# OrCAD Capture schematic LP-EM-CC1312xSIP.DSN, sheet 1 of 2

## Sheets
1 1_RF and Peripherals: size A3; title: LP-EM-CC1312PSIP
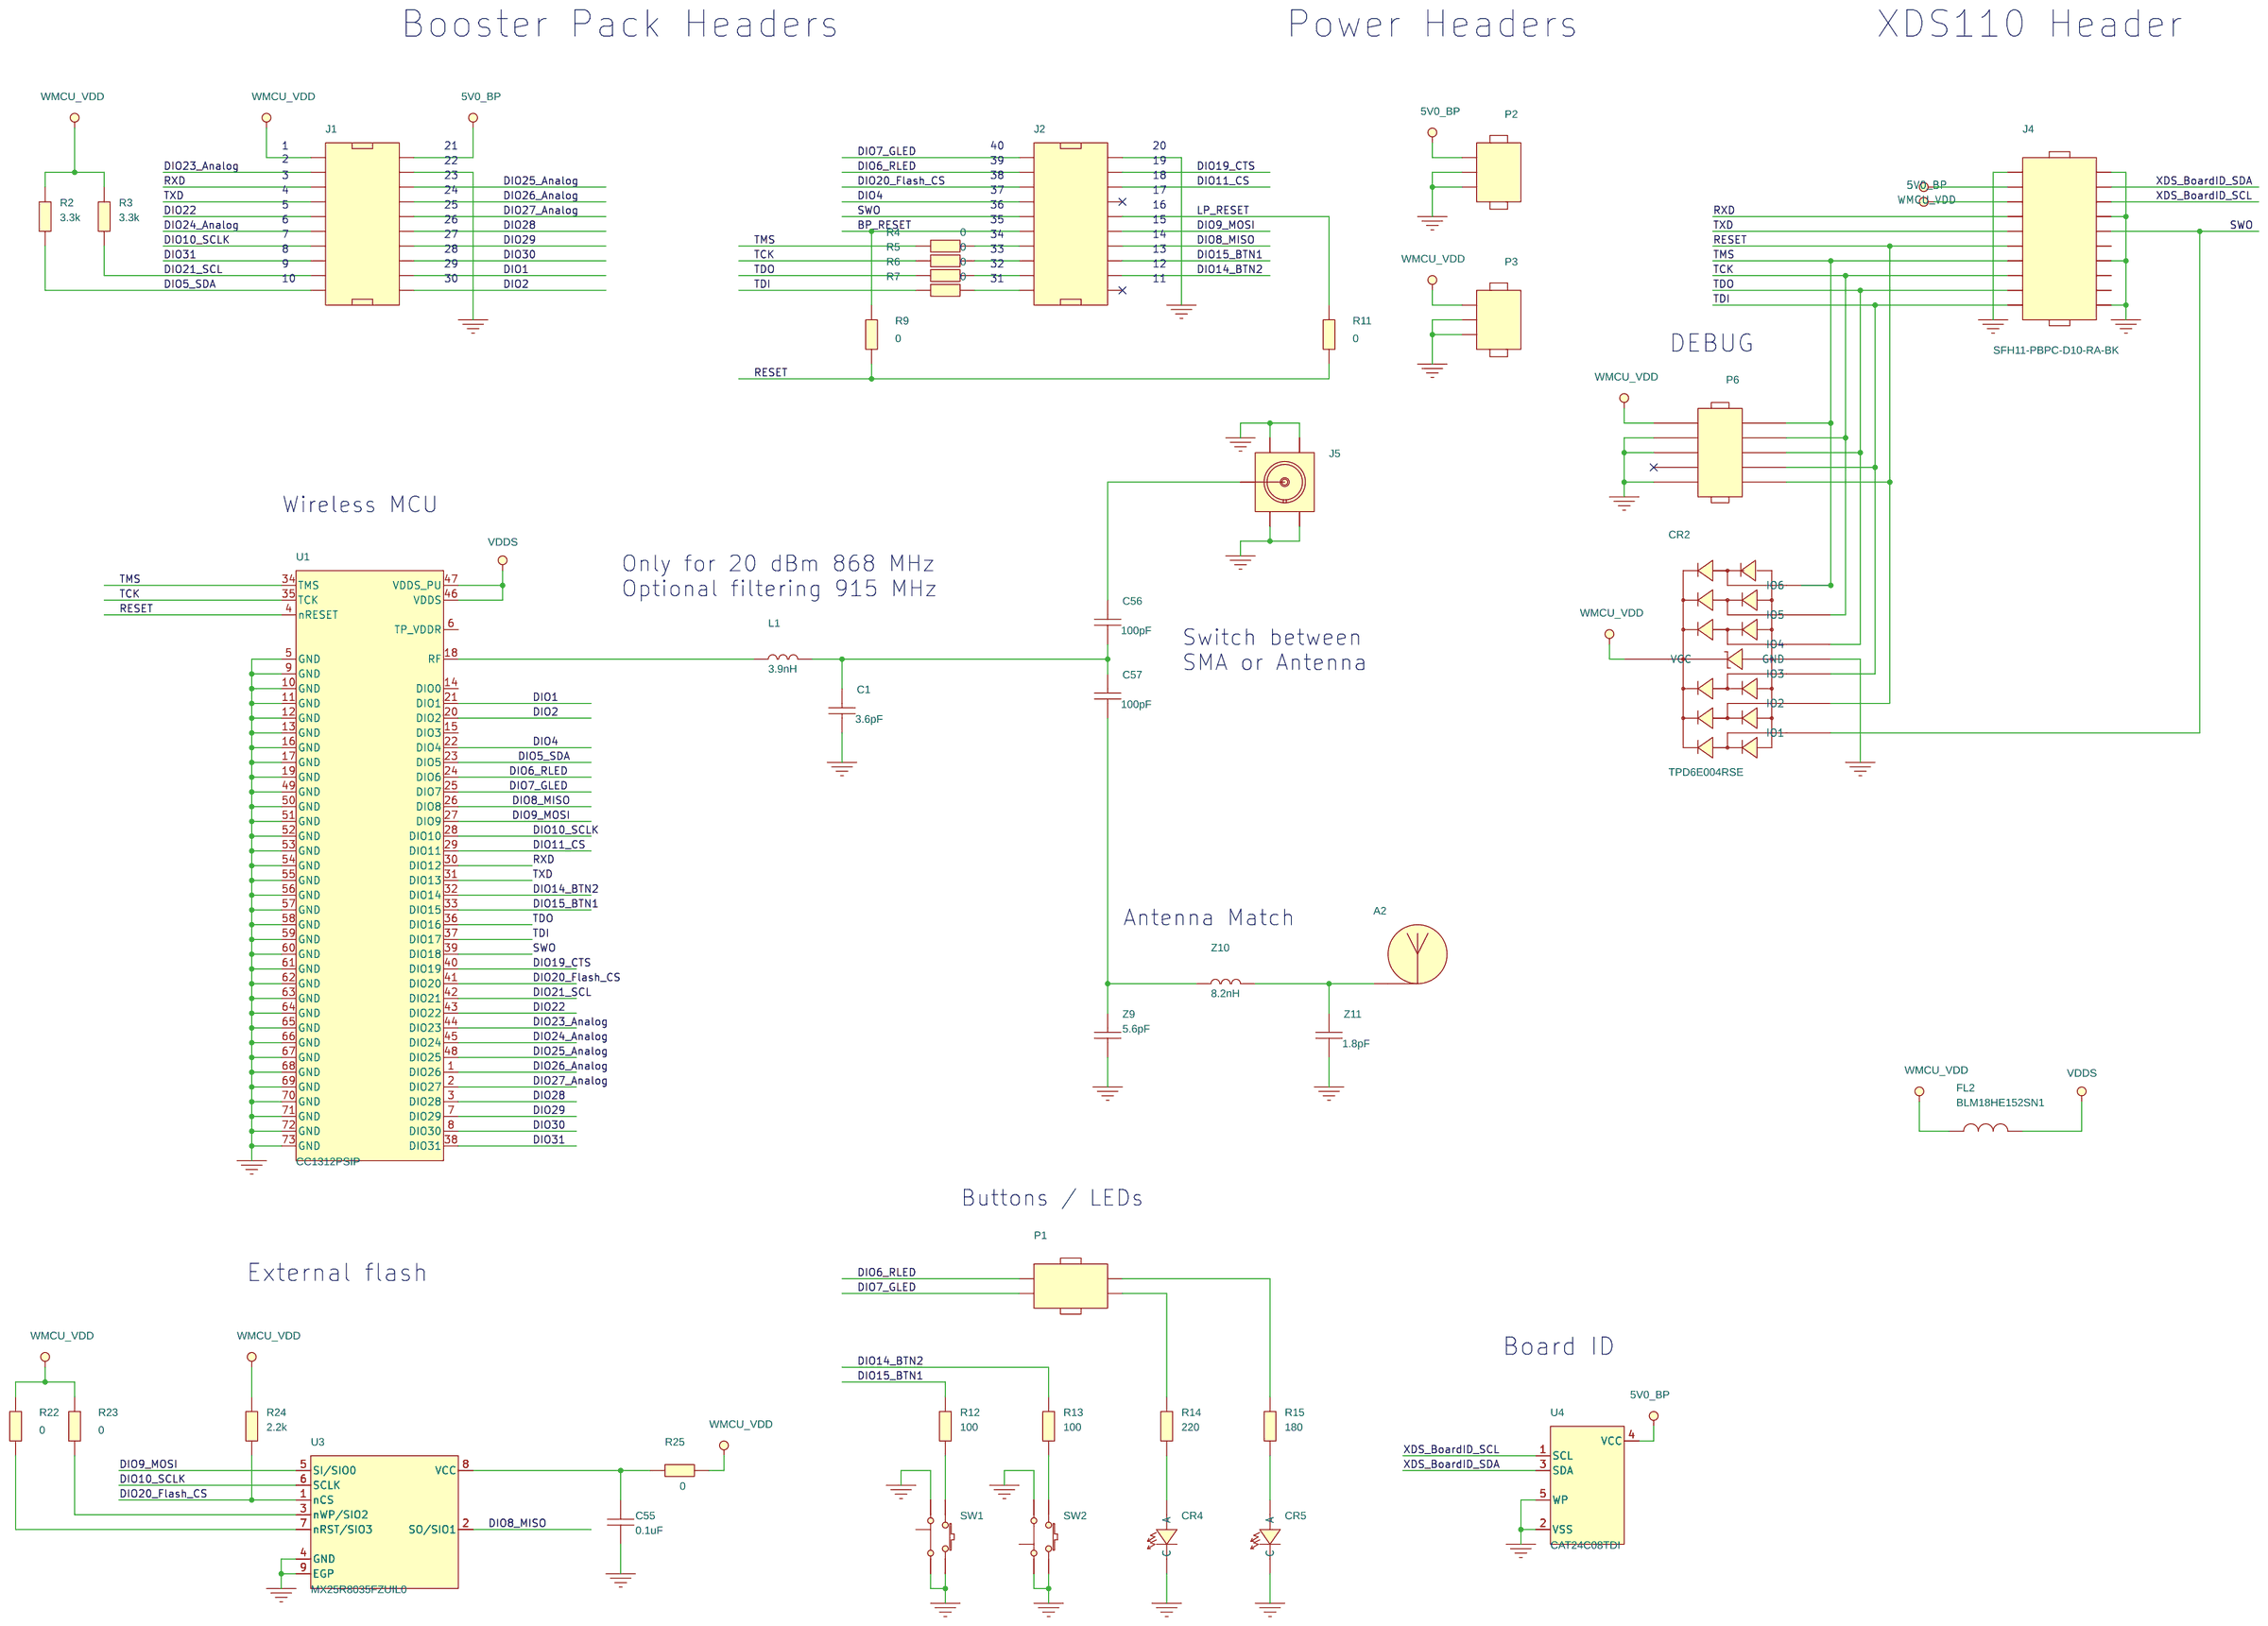
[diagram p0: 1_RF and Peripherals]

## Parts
A2  868MHz/2440MHz  [ANTENNA_DN024N]
C1  3.6pF  [CAPC0603X35B2N]
C55  0.1uF  [CAPC0603X35B2N]
C56  100pF  [CAPC0603X35B2N]
C57  100pF  [CAPC0603X35B2N]
CR2  TPD6E004RSE  [QFNFC50P150X150X60-8A2N]
CR4  LPL296-J2L2-25  [LEDC1707X65N]
CR5  LS L296-P2Q2-1  [LEDC1708X67N]
FL2  BLM18HE152SN1  [FIL_BLM18HE152SN1DN]
J1  SSQ-110-23-L-D  [SAMTEC_SSQ11023LD_A2B]
J2  SSQ-110-23-L-D  [SAMTEC_SSQ11023LD_A2B]
J4  SFH11-PBPC-D10-RA-BK  [SULLINS_SFH11PBPCD10RABK_A2B]
J5  SMA-10V21-TGG  [HUSTSAN_SMA10V21TGGAN]
L1  3.9nH  [INDC0603X33A2N]
P1  BB02-HJ041-KB1-603000  [GRADCONN_BB02HJ041KB1603000_A2B]
P2  BB02-HC031-KB1-603000  [GRADCONN_BB02HC031KB1603000_A2B]
P3  BB02-HC031-KB1-603000  [GRADCONN_BB02HC031KB1603000_A2B]
P6  FTSH-105-01-F-DV-K  [SAMTEC_FTSH10501FDVK_A2N]
R2  3.3k  [RESC1005X40B2N]
R3  3.3k  [RESC1005X40B2N]
R4  0  [RESC0603X35B2N]
R5  0  [RESC0603X35B2N]
R6  0  [RESC0603X35B2N]
R7  0  [RESC0603X35B2N]
R9  0  [RESC0603X35B2N]
R11  0  [RESC0603X35B2N]
R12  100  [RESC1005X40B2N]
R13  100  [RESC1005X40B2N]
R14  220  [RESC1005X40B2N]
R15  180  [RESC1005X40B2N]
R22  0  [RESC0603X35B2N]
R23  0  [RESC0603X35B2N]
R24  2.2k  [RESC1005X40B2N]
R25  0  [RESC0603X35B2N]
SW1  1188E-1K2  [SW_1188E1K2V_A2N]
SW2  1188E-1K2  [SW_1188E1K2V_A2N]
U1  CC1312PSIP  [LGAFC73S50P700X700X151]
U3  MX25R8035FZUIL0  [SON50P300X200X60-9B2N]
U4  CAT24C08TDI  [SOT95P280X100-5A2N]
Z9  5.6pF  [CAPC0603X35B2N]
Z10  8.2nH  [INDC0603X33A2N]
Z11  1.8pF  [CAPC0603X35B2N]

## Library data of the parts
A2 = ANTENNA_PCB: ANTENNA, NON COMPONENT, DUAL BAND OPTION - 868MHz/2440MHz, NOT APPLY; Additional Datasheet URL: N/A; AutoDoc File: https://notefied-dynamic-precision.com/DB/Apps/Desktop/Item/Object.aspx?id=96668; BU Name: DYNAMIC PRECISION GDANSK; Budget Currency: N/A; Budget Price: N/A; Client Status: UNDER_REVIEW; Country of Origin: Missing Info; Datasheet URL: https://www.ti.com/lit/an/swra227e/swra227e.pdf; Datasheet URL 1: http://www.ti.com/lit/an/swra227e/swra227e.pdf; Datasheet URL 2: N/A; Exclusive for Customers: TEXAS INSTRUMENTS NORWAY; Mass: N/A; Max Oper Temp: N/A; Maximum Operating Temperature: N/A; Min Oper Temp: N/A; Minimum Operating Temperature: N/A; Mounting Type: NOT APPLY; NOTEfied URL: https://notefied-dynamic-precision.com/NOTEfiedWebInterface/part/show?partNumber=13-01029; Notes: Custom component designed upon client's request.; Packing Size: N/A; Packing Type: Missing Info; Part Number: 13-01029; Part Type: Mechanic|ANTENNA|NON COMPONENT; ROHS: Missing Info; Revision: R024; RoHS Status: MISSING_INFO; Status: Released; Texas Part Status: Under Review; Type: Mechanic; Vendor: TEXAS INSTRUMENTS; Vendor Part Number: DN024; Vendor Part Status: Active; Weight: N/A
C1 = CAPACITOR: CAPACITOR, CERAMIC C0G/NP0, 3.6pF, 50V, -0.1pF/+0.1pF, -55DEGC/+125DEGC, 0201, SMD; ALT_SYMBOLS: CAPC0603X35B2L,CAPC0603X35B2M; Additional Datasheet URL: https://www.murata.com/en-eu/products/productdetail?partno=GRM0335C1H3R6BA01%23; Country of Origin: China,Japan,Philippines; Datasheet URL: https://search.murata.co.jp/Ceramy/image/img/A01X/G101/ENG/GRM0335C1H3R6BA01-01A.pdf; Dielectric Type: C0G/NP0; Mass: 0.00033g; Maximum Operating Temperature: +125DEGC; Maximum Tolerance: +0.1pF; Minimum Operating Temperature: -55DEGC; Minimum Tolerance: -0.1pF; Mounting Type: SMD; NOTEfied URL: https://notefied-dynamic-precision.com/NOTEfiedWebInterface/part/show?partNumber=02-06150; PCB Package: 0201; Packing Size: 50000; Packing Type: Tape & Reel; Part Number: 02-06150; Part Type: Capacitor|CERAMIC|0201|STANDARD; REACH/SVHC Compliance: Compliant; REACH/SVHC Details: SVHC List Version Jul 7, 2017; REACH/SVHC Source: REACH Declaration; REACH/SVHC Status: Unaffected; ROHS: Compliant; Rated Voltage: 50V; Revision: R037; Status: Released; Texas Part Status: Under Review; Type: Capacitor; Vendor: MURATA; Vendor Part Number: GRM0335C1H3R6BA01J; Vendor Part Status: Active
C55 = CAPACITOR: CAPACITOR, CERAMIC X7S, 0.1uF, 10V, -10%/+10%, -55DEGC/+125DEGC, 0201, SMD; ALT_SYMBOLS: CAPC0603X35B2L,CAPC0603X35B2M; Additional Datasheet URL: https://search.murata.co.jp/Ceramy/image/img/A01X/G101/ENG/GRM033C71A104KE14-01A.pdf; AutoDoc File: https://notefied-dynamic-precision.com/DB/Apps/Desktop/Item/Object.aspx?id=115293; BU Name: TEXAS INSTRUMENTS NORWAY; Budgetary Price: 0.01328 USD; Client Status: UNDER_REVIEW; Datasheet URL: https://www.murata.com/-/media/webrenewal/support/library/catalog/products/capacitor/ceramiccapacitor/c02e.ashx?la=en-gb; Datasheet URL 1: http://psearch.en.murata.com/capacitor/product/GRM155R71E104KE14%23.pdf; Datasheet URL 2: http://search.murata.co.jp/Ceramy/image/img/w_hinm/L0005E.pdf; Definied Quality: INDUSTRIAL; Dielectric Type: X7S; Esd Level: N/A; Lead Time: 23; LifeCycle Status: ACTIVE; MPN: CAPACITOR_0402_100nF_X7R_M_+/-10%_10V; MPN Status: ACTIVE; MSL: N/A; MTBF: N/A; MTBF Standard: N/A; Manufacturer: MANUFACTURER SELECTION; Mass: 0.00033g; Max Oper Temp: +125DEGC; Max Tol: +10%; Maximum Operating Temperature: +125DEGC; Maximum Tolerance: +10%; Min Oper Temp: -55DEGC; Min Tol: -10%; Minimum Operating Temperature: -55DEGC; Minimum Tolerance: -10%; Mounting Type: SMD; NOTE Status: PREFERRED; NOTEfied URL: https://notefied-dynamic-precision.com/NOTEfiedWebInterface/part/show?partNumber=02-10308; Old Footprint: CAPC1005X60N; PCB Package: 0201; Packing Size: 15000; Packing Type: Tape & Reel; Part Number: 02-10308; Part Type: Capacitor|CERAMIC|0201|STANDARD; REACH/SVHC Compliance: Compliant; REACH/SVHC Details: SVHC List Version Jan 19, 2021; REACH/SVHC Source: REACH Declaration; REACH/SVHC Status: Unaffected; REACH/SVHC_COMPLIANCE: COMPLIANT; REACH/SVHC_DETAILS: SVHC LIST VERSION Jun 20, 2016; REACH/SVHC_SOURCE: REACH DECLARATION; REACH/SVHC_STATUS: UNAFFECTED; ROHS: Compliant; Rated Voltage: 10V; Revision: R001; RoHS Status: ROHS_COMPLIANT; Rtd Voltage: 25V; Status: Released; Texas Part Status: Under Review; Type: Capacitor; Vendor: MURATA; Vendor Part Number: GRM033C71A104KE14D; Vendor Part Status: Active; WEIGHT: 0.0016g
C56 C57 = CAPACITOR: CAPACITOR, CERAMIC C0G/NP0, 100pF, 50V, -2%/+2%, -55DEGC/+125DEGC, 0201, SMD; ALT_SYMBOLS: CAPC0603X35B2L,CAPC0603X35B2M; Additional Datasheet URL: https://search.murata.co.jp/Ceramy/image/img/A01X/G101/ENG/GRM0335C1H101GA01-01A.pdf; Budgetary Price: 0.0032 USD; Country of Origin: China,Japan,Philippines; Datasheet URL: https://www.murata.com/-/media/webrenewal/support/library/catalog/products/capacitor/ceramiccapacitor/c02e.ashx?la=en-gb&cvid=20210120024548000000; Dielectric Type: C0G/NP0; Lead Time: 11; Mass: 0.00033g; Maximum Operating Temperature: +125DEGC; Maximum Tolerance: +2%; Minimum Operating Temperature: -55DEGC; Minimum Tolerance: -2%; Mounting Type: SMD; NOTEfied URL: https://notefied-dynamic-precision.com/NOTEfiedWebInterface/part/show?partNumber=02-07975; PCB Package: 0201; Packing Size: 15000; Packing Type: Tape & Reel; Part Number: 02-07975; Part Type: Capacitor|CERAMIC|0201|STANDARD; ROHS: Compliant; Rated Voltage: 50V; Revision: R023; Status: Released; Type: Capacitor; Vendor: MURATA; Vendor Part Number: GRM0335C1H101GA01D; Vendor Part Status: Active
CR2 = DIODE_TVS_TPD6E004_QFN8_V1: DIODE, PROTECTION, ESD ARRAY - 6 CHANNELS, 0.9V TO 5.5V, VBR:7V, -40DEGC/+85DEGC, QFN8, SMD; ALT_SYMBOLS: QFNFC50P150X150X60-8A2L,QFNFC50P150X150X60-8A2M; Additional Datasheet URL: https://www.ti.com/lit/ml/mpqf207e/mpqf207e.pdf; AutoDoc File: https://notefied-dynamic-precision.com/DB/Apps/Desktop/Item/Object.aspx?id=74721; BU Name: DYNAMIC PRECISION GDANSK; Budget Currency: USD; Budget Price: 0.27; Budgetary Price: 0.295 USD; CLASS: IC; Client Status: UNDER_REVIEW; Country of Origin: China,Thailand; Datasheet URL: https://www.ti.com/lit/gpn/tpd6e004; Datasheet URL 1: http://www.ti.com/lit/ds/symlink/tpd6e004.pdf; Datasheet URL 2: http://www.ti.com/litv/pdf/mpqf207b; FPLIST: QFN50P150X150X60-8N,QFN50P150X150X60-8AN; Lead Time: 10; Mass: 0.0033g; Max Oper Temp: +85DEGC; Maximum Operating Temperature: +85DEGC; Min Oper Temp: -40DEGC; Minimum Operating Temperature: -40DEGC; Mounting Type: SMD; NOTEfied URL: https://notefied-dynamic-precision.com/NOTEfiedWebInterface/part/show?partNumber=14-05493; PCB Package: QFN8; Packing Size: 3000; Packing Type: Tape & Reel; Part Number: 14-05493; Part Type: Diode|PROTECTION; REACH/SVHC Compliance: Compliant; REACH/SVHC Details: SVHC List Version Jun 20, 2016; REACH/SVHC Source: Material Declaration; REACH/SVHC Status: Unaffected; ROHS: Compliant; Rated Power: N/A; Rated Voltage: 7V; Revision: R027; RoHS Status: ROHS_COMPLIANT; Rtd Power: N/A; Rtd Voltage: 7V; Status: Released; Texas Part Status: Under Review; Type: Diode; Vendor: TEXAS INSTRUMENTS; Vendor Part Number: TPD6E004RSER; Vendor Part Status: Active; Weight: 0.0033g
CR4 = LED: OPTO, LED, InGaAlP, GREEN, 560nm, 2V, 0.02A, 0603, SMD; ALT_SYMBOLS: LEDC1707X65L,LEDC1707X65M; Additional Datasheet URL: https://www.osram.com/ecat/SMARTLED%C2%AE%200603%20LP%20L296/com/en/class_pim_web_catalog_103489/prd_pim_device_2190983/; AutoDoc File: http://notefied-dynamic-precision.com/DB/Apps/Desktop/Item/Object.aspx?id=81622; Budget Currency: USD; Budget Price: 0.1263; CLASS: IC; Country of Origin: Missing Info; Datasheet URL: https://dammedia.osram.info/media/resource/hires/osram-dam-5662674/LP%20L296_EN.pdf; Datasheet URL 1: N/A; Datasheet URL 2: http://catalog.osram-os.com/jsp/download.jsp?rootPath=/media/&name=LP_L296.pdf&docPath=Graphics/00077128_0.pdf&url=/media//_en/Graphics/00077128_0.pdf; Definied Quality: INDUSTRIAL; Esd Level: HBM 2kV; FPLIST: LEDC1707X65N,LEDC1707X65L,LEDC1707X65M; MPN: LP L296-J2L2-25; MPN Status: NRND; MSL: 2; MTBF: N/A; MTBF Standard: N/A; Manufacturer: OSRAM; Mass: 0.0016g; Max Oper Temp: +100DEGC; Maximum Operating Temperature: +100DEGC; Min Oper Temp: -40DEGC; Minimum Operating Temperature: -40DEGC; Mounting Type: SMD; NOTE Status: NOT_PREFERRED; NOTEfied URL: https://notefied-dynamic-precision.com/NOTEfiedWebInterface/part/show?partNumber=15-01023; PCB Package: 0603; Packing Size: 5000; Packing Type: Tape & Reel; Part Number: 15-01023; Part Type: Opto|LED|0603; REACH/SVHC Compliance: Compliant; REACH/SVHC Details: SVHC List Version Jan 12, 2017; REACH/SVHC Source: REACH Declaration; REACH/SVHC Status: Unaffected; ROHS: Compliant; Rated Current: 0.02A; Rated Voltage: 2V; Revision: R029; RoHS Status: ROHS_COMPLIANT; Rtd Current: 0.02A; Rtd Power: 0.08W; Rtd Voltage: 2V; Status: Released; Type: Opto; Vendor: OSRAM; Vendor Part Number: LP L296-J2L2-25; Vendor Part Status: Active; WEIGHT: 0.002g
CR5 = LED: OPTO, LED, RED, 630nm, 2V, 0.02A, 0603, SMD; ALT_SYMBOLS: LEDC1708X67L,LEDC1708X67M; Additional Datasheet URL: https://www.osram.com/ecat/SMARTLED%C2%AE%200603%20LS%20L296/com/en/class_pim_web_catalog_103489/prd_pim_device_2190979/; AutoDoc File: http://notefied-dynamic-precision.com/DB/Apps/Desktop/Item/Object.aspx?id=88355; Budget Currency: USD; Budget Price: 0.089; CLASS: IC; Country of Origin: Missing Info; Datasheet URL: https://dammedia.osram.info/media/resource/hires/osram-dam-5361494/LS%20L296_EN.pdf; Datasheet URL 1: http://www.osram-os.com/osram_os/en/products/product-catalog/led-light-emitting-diodes/smartled-0603/ls-l296/index.jsp?search_result=%2fosram_os%2fen%2fsearch%2fadvanced_search.jsp%3faction%3ddosearch%26inp_searchterm_1%3dLS%2bL296-P2Q2-1%26website_name%3; Datasheet URL 2: http://www.osram-os.com/Graphics/XPic5/00077119_0.pdf/LS%20L296%20-%20SMARTLED%200603.pdf; Definied Quality: INDUSTRIAL; Esd Level: HBM 2kV; FPLIST: LEDC1708X67N,LEDC1708X67L,LEDC1708X67M; MPN Status: NRND; MSL: 2; MTBF: N/A; MTBF Standard: N/A; Manufacturer: OSRAM; Mass: 0.0016g; Max Oper Temp: +100DEGC; Maximum Operating Temperature: +100DEGC; Min Oper Temp: -40DEGC; Minimum Operating Temperature: -40DEGC; Mounting Type: SMD; NOTE Status: PREFERRED; NOTEfied URL: https://notefied-dynamic-precision.com/NOTEfiedWebInterface/part/show?partNumber=15-01169; PCB Package: 0603; PPCB Recomendation: Inactive for new design [Alert:0001]; Packing Size: 5000; Packing Type: Tape & Reel; Part Number: 15-01169; Part Type: Opto|LED|0603; REACH/SVHC Compliance: Compliant; REACH/SVHC Details: SVHC List Version Jan 12, 2017; REACH/SVHC Source: REACH Declaration; REACH/SVHC Status: Unaffected; ROHS: Compliant; Rated Current: 0.02A; Rated Voltage: 2V; Revision: R029; RoHS Status: ROHS_COMPLIANT; Rtd Current: 0.06A; Rtd Voltage: 1.8V TO 2.3V; Status: Released; Type: Opto; Vendor: OSRAM; Vendor Part Status: Active; WEIGHT: 0.002g
FL2 = FILTER_2PIN: FILTER, EMI, FERRITE BEAD, 1500@100MHz, -25%/+25%, -55DEGC/+125DEGC, 0603, SMD; ALT_SYMBOLS: FIL_BLM18HE152SN1DL,FIL_BLM18HE152SN1DM; Additional Datasheet URL: https://www.murata.com/en-eu/products/productdata/8796741599262/ENFA0004.pdf?1602473425000; AutoDoc File: http://notefied-dynamic-precision.com/DB/Apps/Desktop/Item/Object.aspx?id=85575; Budget Currency: EUR; Budget Price: 0.085; Budgetary Price: 0.07 EUR; CLASS: IC; Country of Origin: Japan,Singapore,Thailand; Datasheet URL: https://www.murata.com/~/media/webrenewal/support/library/catalog/products/emc/emifil/c31e.ashx; Datasheet URL 1: http://search.murata.co.jp/Ceramy/image/img/PDF/ENG/L0110S0101BLM18H.pdf; Datasheet URL 2: http://search.murata.co.jp/Ceramy/image/img/PDF/ENG/L0110S0101BLM18H.pdf; FPLIST: FIL_BLM18HE152SN1DN,FIL_BLM18HE152SN1DL,FIL_BLM18HE152SN1DM; Frequency: 100MHz; Impedance: 1500; Inductance: N/A; Lead Time: 8; MPN: BLM18HE152SN1D; MPN Status: ACTIVE; Manufacturer: MURATA; Mass: 0.006g; Max Oper Temp: +125DEGC; Max Tol: +25%; Maximum Operating Temperature: +125DEGC; Maximum Tolerance: +25%; Min Oper Temp: -55DEGC; Min Tol: -25%; Minimum Operating Temperature: -55DEGC; Minimum Tolerance: -25%; Mounting Type: SMD; NOTE Status: PREFERRED; NOTEfied URL: https://notefied-dynamic-precision.com/NOTEfiedWebInterface/part/show?partNumber=04-00470; PCB Package: 0603; Packing Size: 4000; Packing Type: Tape & Reel; Part Number: 04-00470; Part Type: Filter|EMI|FERRITE BEAD|0603; REACH/SVHC Compliance: Compliant; REACH/SVHC Details: SVHC List Version Jul 7, 2017; REACH/SVHC Source: REACH Declaration; REACH/SVHC Status: Unaffected; ROHS: Compliant; Rated Current: 0.5A; Rated Voltage: N/A; Revision: R023; RoHS Status: ROHS_COMPLIANT; Rtd Current: 0.5A; Status: Released; Texas Part Status: Under Review; Type: Filter; Vendor: MURATA; Vendor Part Number: BLM18HE152SN1D; Vendor Part Status: Active; WEIGHT: 0.006g
J1 J2 = CONN_HEADER_2X10_J_S_V1: CONNECTOR, HEADER, FEMALE, STRAIGHT, 2 ROWS, 20 PINS, 2.54mm, PTH; ALT_SYMBOLS: SAMTEC_SSQ11023LD_A2C,SAMTEC_SSQ11023LD_A2A; Additional Datasheet URL: https://suddendocs.samtec.com/prints/ssq-1xx-xx-xxx-x-xx-xxx-xx-x-mkt.pdf; AutoDoc File: http://notefied-dynamic-precision.com/DB/Apps/Desktop/Item/Object.aspx?id=104387; Budget Currency: USD; Budget Price: 2.14; Budgetary Price: 3.17 USD; Country of Origin: China,Costa Rica,Malaysia,Singapore,United States; Datasheet URL: https://suddendocs.samtec.com/catalog_english/ssq_th.pdf; Datasheet URL 1: http://suddendocs.samtec.com/prints/ssq-1xx-xx-xxx-x-xx-xxx-xx-x-mkt.pdf; Datasheet URL 2: http://suddendocs.samtec.com/catalog_english/ssq_th.pdf; Definied Quality: INDUSTRIAL; Esd Level: N/A; FPLIST: SAMTEC_SSQ11023LD_A2B,SAMTEC_SSQ11023LD_A2C,SAMTEC_SSQ11023LD_A2A; LifeCycle Status: ACTIVE; MPN Status: ACTIVE; MSL: N/A; Manufacturer: SAMTEC; Mass: 2.45594g; Max Oper Temp: +125DEGC; Maximum Operating Temperature: +125DEGC; Min Oper Temp: -55DEGC; Minimum Operating Temperature: -55DEGC; Mounting Type: PTH; NOTE Status: PREFERRED; NOTEfied URL: https://notefied-dynamic-precision.com/NOTEfiedWebInterface/part/show?partNumber=06-04997; No Of Pos: 20; No Of Rows: 2; Number of Positions: 20; Number of Rows: 2; Packing Size: 21; Packing Type: Bulk; Part Number: 06-04997; Part Type: Connector|HEADER|STANDARD; Pitch: 2.54mm; REACH/SVHC Compliance: Compliant; REACH/SVHC Details: SVHC List Version Jan 12, 2017; REACH/SVHC Source: REACH Declaration; REACH/SVHC Status: Unaffected; ROHS: Compliant; Rated Current: 6.3A; Revision: R020; RoHS Status: ROHS_COMPLIANT; Rtd Current: 6.3A; Status: Released; Texas Part Status: Under Review; Type: Connector; Vendor: SAMTEC; Vendor Part Status: Active; WEIGHT: 2.45594g
J4 = CONN_HEADER_2X10_P_V3: CONNECTOR, HEADER, FEMALE, RIGHT ANGLE, 2 ROW(S), 20 PINS, PITCH 2.54mm, PTH; ALT_SYMBOLS: SULLINS_SFH11PBPCD10RABK_A2A,SULLINS_SFH11PBPCD10RABK_A2C; Additional Datasheet URL: https://s3.amazonaws.com/catalogspreads-pdf/PAGE123%20.100%20SFH11%20SERIES%20FEMALE%20HDR%20ST%20RA.pdf; Datasheet URL: https://drawings-pdf.s3.amazonaws.com/11161.pdf; Mass: N/A; Maximum Operating Temperature: +105DEGC; Minimum Operating Temperature: -40DEGC; Mounting Type: PTH; NOTEfied URL: https://notefied-dynamic-precision.com/NOTEfiedWebInterface/part/show?partNumber=06-12237; Number of Positions: 20; Number of Rows: 2; Packing Size: N/A; Packing Type: Missing Info; Part Number: 06-12237; Part Type: Connector|HEADER|STANDARD; Pitch: 2.54mm; REACH/SVHC Compliance: Compliant; REACH/SVHC Details: SVHC List Version Jan 17, 2022; REACH/SVHC Source: REACH Declaration; REACH/SVHC Status: Unaffected; ROHS: Compliant; Rated Current: 3A; Rated Voltage: N/A; Revision: R001; Status: Released; Texas Part Status: Under Review; Type: Connector; Vendor: SULLINS; Vendor Part Status: Active
J5 = CONN_COAX_1_4: CONNECTOR, COAX, RF, FEMALE, STRAIGHT, 1 PIN, SMD; ALT_SYMBOLS: HUSTSAN_SMA10V21TGGL,HUSTSAN_SMA10V21TGGM; Additional Datasheet URL: http://www.hustsan.com.tw/cgi-bin/productfn/pdt_detail_lst.pl?ProdID=143; AutoDoc File: https://notefied-dynamic-precision.com/DB/Apps/Desktop/Item/Object.aspx?id=84956; BU Name: DYNAMIC PRECISION GDANSK; Budget Currency: N/A; Budget Price: N/A; Client Status: UNDER_REVIEW; Country of Origin: Taiwan; Datasheet URL: http://www.hustsan.com.tw/uploaddir/product/SMA-10V21.pdf; Datasheet URL 1: http://www.hustsan.com.tw/uploaddir/product/SMA-10V21.pdf; Datasheet URL 2: http://www.hustsan.com.tw/cgi-bin/productfn/pdt_detail_lst.pl?ProdID=143; FPLIST: HUSTSAN_SMA10V21TGGAN,HUSTSAN_SMA10V21TGGN; Mass: N/A; Mounting Type: SMD; NOTEfied URL: https://notefied-dynamic-precision.com/NOTEfiedWebInterface/part/show?partNumber=06-02188; No Of Pos: 1; Number of Positions: 1; Packing Size: 350; Packing Type: Tape & Reel; Part Number: 06-02188; Part Type: Connector|COAX|RF; REACH/SVHC Compliance: Compliant; REACH/SVHC Details: SVHC List Version Jun 20, 2016; REACH/SVHC Source: REACH Declaration; REACH/SVHC Status: Unaffected; REACH/SVHC_COMPLIANCE: COMPLIANT; REACH/SVHC_DETAILS: SVHC LIST VERSION Jan 12, 2016; REACH/SVHC_SOURCE: REACH DECLARATION; REACH/SVHC_STATUS: UNAFFECTED; ROHS: Compliant; Revision: R022; RoHS Status: ROHS_COMPLIANT; Status: Released; Texas Part Status: Under Review; Type: Connector; Vendor: HUS-TSAN; Vendor Part Status: Active; Weight: N/A
L1 = INDUCTOR: INDUCTOR, RF, CHIP, 3.9nH, -0.1nH/+0.1nH, 0.4A, -55DEGC/+125DEGC, 0201, SMD; ALT_SYMBOLS: INDC0603X33A2L,INDC0603X33A2M; Additional Datasheet URL: https://www.murata.com/en-eu/products/productdetail?partno=LQP03TN3N9BZ2%23; Country of Origin: Missing Info; Datasheet URL: https://search.murata.co.jp/Ceramy/image/img/P02/JELF243C-9101.pdf; Frequency: 7900MHz; Mass: 0.0002g; Maximum Operating Temperature: +125DEGC; Maximum Tolerance: +0.1nH; Minimum Operating Temperature: -55DEGC; Minimum Tolerance: -0.1nH; Mounting Type: SMD; NOTEfied URL: https://notefied-dynamic-precision.com/NOTEfiedWebInterface/part/show?partNumber=03-08385; PCB Package: 0201; Packing Size: 15000; Packing Type: Tape & Reel; Part Number: 03-08385; Part Type: Inductor|RF|CHIP|0201; REACH/SVHC Compliance: Compliant; REACH/SVHC Details: SVHC List Version Jul 08, 2021; REACH/SVHC Source: REACH Declaration; REACH/SVHC Status: Unaffected; ROHS: Compliant; Rated Current: 0.4A; Resistance: 0.3; Revision: R010; Status: Released; Texas Part Status: Under Review; Type: Inductor; Vendor: MURATA; Vendor Part Number: LQP03TN3N9BZ2D; Vendor Part Status: Active
P1 = CONN_HEADER_2X2_P: CONNECTOR, HEADER, MALE, STRAIGHT, 2 ROWS, 4 PINS, PITCH 2.54mm, PTH; ALT_SYMBOLS: GRADCONN_BB02HJ041KB1603000_A2C,GRADCONN_BB02HJ041KB1603000_A2A; Additional Datasheet URL: https://www.gradconn.com/Files/Drawings/BB02-HJ.pdf; AutoDoc File: http://notefied-dynamic-precision.com/DB/Apps/Desktop/Item/Object.aspx?id=104391; Country of Origin: Missing Info; Datasheet URL: https://www.gradconn.com/Files/Specs/BTB-2.54mm-Header-specification.pdf; Datasheet URL 1: http://www.gradconn.com/Files/Drawings/BB02-HJ.pdf; Datasheet URL 2: http://www.gradconn.com/Files/Specs/BTB-2.54mm-Header-specification.pdf; FPLIST: GRADCONN_BB02HJ041KB1603000_A2B,GRADCONN_BB02HJ041KB1603000_A2C,GRADCONN_BB02HJ041KB1603000_A2A; MPN Status: ACTIVE; Manufacturer: GRADCONN; Mass: N/A; Max Oper Temp: +105DEGC; Maximum Operating Temperature: +105DEGC; Min Oper Temp: -40DEGC; Minimum Operating Temperature: -40DEGC; Mounting Type: PTH; NOTE Status: PREFERRED; NOTEfied URL: https://notefied-dynamic-precision.com/NOTEfiedWebInterface/part/show?partNumber=06-04999; No Of Pos: 4; No Of Rows: 2; Number of Positions: 4; Number of Rows: 2; Packing Size: N/A; Packing Type: Missing Info; Part Number: 06-04999; Part Type: Connector|HEADER|STANDARD; Pitch: 2.54mm; REACH/SVHC Compliance: Compliant; REACH/SVHC Details: SVHC List Version Jun 20, 2016; REACH/SVHC Source: RoHS & REACH Declaration; REACH/SVHC Status: Unaffected; ROHS: Compliant; Rated Current: 3A; Revision: R021; RoHS Status: ROHS_COMPLIANT; Rtd Current: 3A; Status: Released; Texas Part Status: Under Review; Type: Connector; Vendor: GRADCONN; Vendor Part Status: Active
P2 P3 = CONN_HEADER_3_P_S: CONNECTOR, HEADER, MALE, STRAIGHT, 1 ROW, 3 PINS, PITCH 2.54mm, PTH; ALT_SYMBOLS: GRADCONN_BB02HC031KB1603000_A2C,GRADCONN_BB02HC031KB1603000_A2A; Additional Datasheet URL: https://www.gradconn.com/Files/Drawings/BB02-HC.pdf; AutoDoc File: http://notefied-dynamic-precision.com/DB/Apps/Desktop/Item/Object.aspx?id=104636; Country of Origin: Missing Info; Datasheet URL: https://www.gradconn.com/Files/Specs/BTB-2.54mm-Header-specification.pdf; Datasheet URL 1: http://www.gradconn.com/Files/Drawings/BB02-HC.pdf; Datasheet URL 2: http://www.gradconn.com/Files/Specs/BTB-2.54mm-Header-specification.pdf; FPLIST: GRADCONN_BB02HC031KB1603000_A2B,GRADCONN_BB02HC031KB1603000_A2C,GRADCONN_BB02HC031KB1603000_A2A; MPN Status: ACTIVE; Manufacturer: GRADCONN; Mass: N/A; Max Oper Temp: +105DEGC; Maximum Operating Temperature: +105DEGC; Min Oper Temp: -40DEGC; Minimum Operating Temperature: -40DEGC; Mounting Type: PTH; NOTE Status: PREFERRED; NOTEfied URL: https://notefied-dynamic-precision.com/NOTEfiedWebInterface/part/show?partNumber=06-05038; No Of Pos: 3; No Of Rows: 1; Number of Positions: 3; Number of Rows: 1; Packing Size: N/A; Packing Type: Missing Info; Part Number: 06-05038; Part Type: Connector|HEADER|STANDARD; Pitch: 2.54mm; REACH/SVHC Compliance: Compliant; REACH/SVHC Details: SVHC List Version Jun 20, 2016; REACH/SVHC Source: RoHS & REACH Declaration; REACH/SVHC Status: Unaffected; ROHS: Compliant; Rated Current: 3A; Rated Voltage: 250V; Revision: R021; RoHS Status: ROHS_COMPLIANT; Rtd Current: 3A; Rtd Voltage: 250V; Status: Released; Texas Part Status: Under Review; Type: Connector; Vendor: GRADCONN; Vendor Part Status: Active
P6 = CONN_HEADER_2X5: CONNECTOR, HEADER, MALE, STRAIGHT, 2 ROWS, 10 PINS, PITCH 1.27mm, SMD; ALT_SYMBOLS: SAMTEC_FTSH10501FDVK_A2L,SAMTEC_FTSH10501FDVK_A2M; Additional Datasheet URL: https://suddendocs.samtec.com/prints/ftsh-1xx-xx-xxx-dv-xxx-xxx-mkt.pdf; AutoDoc File: http://notefied-dynamic-precision.com/DB/Apps/Desktop/Item/Object.aspx?id=50836; Budget Currency: USD; Budget Price: 1.700; Budgetary Price: 1.682 USD; CLASS: IO; Country of Origin: China,Costa Rica,Malaysia,Singapore,Taiwan,United States,Vietnam; Datasheet URL: https://suddendocs.samtec.com/catalog_english/ftsh_smt.pdf; Datasheet URL 1: http://www.samtec.com/documents/webfiles/cpdf/FTSH-1XX-XX-XXX-DV-XXX-MKT.pdf; Datasheet URL 2: http://www.samtec.com/documents/webfiles/pdf/FTSH_SMT.PDF; FPLIST: SAMTEC_FTSH-105-01-F-DV-K-10N,SAMTEC_FTSH-105-01-F-DV-K-10L,SAMTEC_FTSH-105-01-F-DV-K-10M; LifeCycle Status: MATURITY; MPN Status: ACTIVE; Manufacturer: SAMTEC; Mass: 0.31701g; Max Oper Temp: +125DEGC; Maximum Operating Temperature: +125DEGC; Min Oper Temp: -55DEGC; Minimum Operating Temperature: -55DEGC; Mounting Type: SMD; NOTE Status: PREFERRED; NOTEfied URL: https://notefied-dynamic-precision.com/NOTEfiedWebInterface/part/show?partNumber=06-00166; No Of Pos: 10; No Of Rows: 2; Number of Positions: 10; Number of Rows: 2; Old Footprint: SAMTEC_FTSH-105-01-F-DV-K-10N,CONN_MALE_2X5; Packing Size: 92; Packing Type: Tube; Part Number: 06-00166; Part Type: Connector|HEADER|STANDARD; Pitch: 1.27mm; REACH/SVHC Compliance: Compliant; REACH/SVHC Details: SVHC List Version Jun 20, 2016; REACH/SVHC Source: Material Declaration; REACH/SVHC Status: Unaffected; ROHS: Compliant; Rated Current: 3.4A; Revision: R029; RoHS Status: ROHS_COMPLIANT; Rtd Current: 1.75A; Status: Released; Texas Part Status: Under Review; Type: Connector; Vendor: SAMTEC; Vendor Part Status: Active; WEIGHT: 0.65614g
R2 R3 = RESISTOR: RESISTOR, THICK FILM, 3.3k, -5%/+5%, 0.063W, 50V, -55DEGC/+155DEGC, 0402, SMD; Additional Datasheet URL: N/A; AutoDoc File: https://notefied-dynamic-precision.com/DB/Apps/Desktop/Item/Object.aspx?id=114561; BU Name: TEXAS INSTRUMENTS NORWAY; Budget Currency: EUR; Budget Price: 0.014; Budgetary Price: 0.014 EUR; Client Status: UNDER_REVIEW; Country of Origin: Israel; Datasheet URL: https://www.vishay.com/docs/20035/dcrcwe3.pdf; Datasheet URL 1: http://www.vishay.com/docs/20035/dcrcwe3.pdf; Datasheet URL 2: N/A; Definied Quality: INDUSTRIAL; Esd Level: N/A; Exclusive for Customers: TEXAS INSTRUMENTS NORWAY; Lead Time: 18; LifeCycle Status: ACTIVE; MPN: RESISTOR_0402_3.3k_+/-5%_50V_0.063W_M_+/-200ppm; MPN Status: ACTIVE; MSL: N/A; MTBF: N/A; MTBF Standard: N/A; Manufacturer: MANUFACTURER SELECTION; Mass: 0.00065g; Max Oper Temp: +155DEGC; Max TC: +200PPM/DEGC; Max Tol: +5%; Maximum Operating Temperature: +155DEGC; Maximum Temperature Coefficient: +200PPM/DEGC; Maximum Tolerance: +5%; Min Oper Temp: -55DEGC; Min TC: -200PPM/DEGC; Min Tol: -5%; Minimum Operating Temperature: -55DEGC; Minimum Temperature Coeficient: -200PPM/DEGC; Minimum Tolerance: -5%; Mounting Type: SMD; NOTE Status: PREFERRED; NOTEfied URL: https://notefied-dynamic-precision.com/NOTEfiedWebInterface/part/show?partNumber=01-22488; Notes: Standard item: Duplicate Reason: custom footprint for TEXAS INSTRUMENTS NORWAY.; Old Footprint: RESC1005X40N; PCB Package: 0402; Packing Size: 10000; Packing Type: Tape & Reel; Part Number: 01-22488; Part Type: Resistor|0402|STANDARD; REACH/SVHC Compliance: Compliant; REACH/SVHC Details: SVHC List Version Jun 20, 2016; REACH/SVHC Source: Material Declaration; REACH/SVHC Status: Unaffected; REACH/SVHC_COMPLIANCE: COMPLIANT; REACH/SVHC_DETAILS: SVHC LIST VERSION Jun 20, 2016; REACH/SVHC_SOURCE: MATERIAL DECLARATION; REACH/SVHC_STATUS: UNAFFECTED; ROHS: Exempt; Rated Current: N/A; Rated Power: 0.063W; Rated Voltage: 50V; Resistor Type: THICK FILM; Revision: R021; RoHS Status: ROHS_COMPLIANT; Rtd Current: N/A; Rtd Power: 0.063W; Rtd Voltage: 50V; Status: Released; Texas Part Status: Under Review; Type: Resistor; Vendor: VISHAY; Vendor Part Number: CRCW04023K30JNED; Vendor Part Status: Active; WEIGHT: 0.00065g
R4-R7 R9 R11 R22 R23 R25 = RESISTOR: RESISTOR, THICK FILM, 0, 0R/+0.05R, 0.05W, 1A, -55DEGC/+155DEGC, 0201, SMD; ALT_SYMBOLS: RESC0603X35B2L,RESC0603X35B2M; Additional Datasheet URL: N/A; Budgetary Price: 0.006 EUR; Country of Origin: Israel,Taiwan; Datasheet URL: https://www.vishay.com/docs/20052/crcw0201e3.pdf; Lead Time: 20; Mass: 0.00017g; Maximum Operating Temperature: +155DEGC; Maximum Temperature Coefficient: N/A; Maximum Tolerance: +0.05R; Minimum Operating Temperature: -55DEGC; Minimum Temperature Coeficient: N/A; Minimum Tolerance: 0R; Mounting Type: SMD; NOTEfied URL: https://notefied-dynamic-precision.com/NOTEfiedWebInterface/part/show?partNumber=01-04043; PCB Package: 0201; Packing Size: 10000; Packing Type: Tape & Reel; Part Number: 01-04043; Part Type: Resistor|0201|JUMPER; REACH/SVHC Compliance: Compliant; REACH/SVHC Details: SVHC List Version Dec 17, 2015; REACH/SVHC Source: Material Declaration; REACH/SVHC Status: Unaffected; ROHS: Exempt; Rated Current: 1A; Rated Power: 0.05W; Rated Voltage: N/A; Resistor Type: THICK FILM; Revision: R027; Status: Released; Type: Resistor; Vendor: VISHAY; Vendor Part Number: CRCW02010000Z0ED; Vendor Part Status: Active
R12 R13 = RESISTOR: RESISTOR, THICK FILM, 100, -5%/+5%, 0.063W, 50V, -55DEGC/+155DEGC, 0402, SMD; Additional Datasheet URL: N/A; AutoDoc File: https://notefied-dynamic-precision.com/DB/Apps/Desktop/Item/Object.aspx?id=114555; BU Name: TEXAS INSTRUMENTS NORWAY; Budget Currency: USD; Budget Price: 0.0014; Budgetary Price: 0.0014 USD; Client Status: UNDER_REVIEW; Country of Origin: United States; Datasheet URL: https://www.vishay.com/docs/20035/dcrcwe3.pdf; Datasheet URL 1: http://www.vishay.com/docs/20035/dcrcwe3.pdf; Datasheet URL 2: N/A; Definied Quality: INDUSTRIAL; Esd Level: N/A; Exclusive for Customers: TEXAS INSTRUMENTS NORWAY; Lead Time: 16; LifeCycle Status: ACTIVE; MPN: RESISTOR_0402_100_+/-5%_50V_0.063W_M_+/-200ppm; MPN Status: ACTIVE; MSL: N/A; MTBF: N/A; MTBF Standard: N/A; Manufacturer: MANUFACTURER SELECTION; Mass: 0.00065g; Max Oper Temp: +155DEGC; Max TC: +200PPM/DEGC; Max Tol: +5%; Maximum Operating Temperature: +155DEGC; Maximum Temperature Coefficient: +200PPM/DEGC; Maximum Tolerance: +5%; Min Oper Temp: -55DEGC; Min TC: -200PPM/DEGC; Min Tol: -5%; Minimum Operating Temperature: -55DEGC; Minimum Temperature Coeficient: -200PPM/DEGC; Minimum Tolerance: -5%; Mounting Type: SMD; NOTE Status: PREFERRED; NOTEfied URL: https://notefied-dynamic-precision.com/NOTEfiedWebInterface/part/show?partNumber=01-22482; Notes: Standard item: Duplicate Reason: custom footprint for TEXAS INSTRUMENTS NORWAY.; Old Footprint: RESC1005X40N; PCB Package: 0402; Packing Size: 10000; Packing Type: Tape & Reel; Part Number: 01-22482; Part Type: Resistor|0402|STANDARD; REACH/SVHC Compliance: Compliant; REACH/SVHC Details: SVHC List Version Jun 20, 2016; REACH/SVHC Source: Material Declaration; REACH/SVHC Status: Unaffected; REACH/SVHC_COMPLIANCE: COMPLIANT; REACH/SVHC_DETAILS: SVHC LIST VERSION Jun 20, 2016; REACH/SVHC_SOURCE: MATERIAL DECLARATION; REACH/SVHC_STATUS: UNAFFECTED; ROHS: Exempt; Rated Current: N/A; Rated Power: 0.063W; Rated Voltage: 50V; Resistor Type: THICK FILM; Revision: R024; RoHS Status: ROHS_COMPLIANT; Rtd Current: N/A; Rtd Power: 0.063W; Rtd Voltage: 50V; Status: Released; Texas Part Status: Under Review; Type: Resistor; Vendor: VISHAY; Vendor Part Number: CRCW0402100RJNED; Vendor Part Status: Active; WEIGHT: 0.00065g
R14 = RESISTOR: RESISTOR, THICK FILM, 220, -5%/+5%, 0.063W, 50V, -55DEGC/+155DEGC, 0402, SMD; Additional Datasheet URL: N/A; AutoDoc File: https://notefied-dynamic-precision.com/DB/Apps/Desktop/Item/Object.aspx?id=113319; BU Name: TEXAS INSTRUMENTS NORWAY; Budget Currency: EUR; Budget Price: 0.014; Budgetary Price: 0.014 EUR; Client Status: UNDER_REVIEW; Country of Origin: Israel; Datasheet URL: https://www.vishay.com/docs/20035/dcrcwe3.pdf; Datasheet URL 1: http://www.vishay.com/docs/20035/dcrcwe3.pdf; Datasheet URL 2: N/A; Definied Quality: INDUSTRIAL; Esd Level: N/A; Exclusive for Customers: TEXAS INSTRUMENTS NORWAY; Lead Time: 18; LifeCycle Status: ACTIVE; MPN: RESISTOR_0402_220_+/-5%_50V_0.063W_M_+/-200ppm; MPN Status: ACTIVE; MSL: N/A; MTBF: N/A; MTBF Standard: N/A; Manufacturer: MANUFACTURER SELECTION; Mass: 0.00065g; Max Oper Temp: +155DEGC; Max TC: +200PPM/DEGC; Max Tol: +5%; Maximum Operating Temperature: +155DEGC; Maximum Temperature Coefficient: +200PPM/DEGC; Maximum Tolerance: +5%; Min Oper Temp: -55DEGC; Min TC: -200PPM/DEGC; Min Tol: -5%; Minimum Operating Temperature: -55DEGC; Minimum Temperature Coeficient: -200PPM/DEGC; Minimum Tolerance: -5%; Mounting Type: SMD; NOTE Status: PREFERRED; NOTEfied URL: https://notefied-dynamic-precision.com/NOTEfiedWebInterface/part/show?partNumber=01-22346; Notes: Standard item: Duplicate Reason: custom footprint for TEXAS INSTRUMENTS NORWAY.; Old Footprint: RESC1005X40N; PCB Package: 0402; Packing Size: 10000; Packing Type: Tape & Reel; Part Number: 01-22346; Part Type: Resistor|0402|STANDARD; REACH/SVHC Compliance: Compliant; REACH/SVHC Details: SVHC List Version Jun 20, 2016; REACH/SVHC Source: Material Declaration; REACH/SVHC Status: Unaffected; REACH/SVHC_COMPLIANCE: COMPLIANT; REACH/SVHC_DETAILS: SVHC LIST VERSION Jun 20, 2016; REACH/SVHC_SOURCE: MATERIAL DECLARATION; REACH/SVHC_STATUS: UNAFFECTED; ROHS: Exempt; Rated Current: N/A; Rated Power: 0.063W; Rated Voltage: 50V; Resistor Type: THICK FILM; Revision: R021; RoHS Status: ROHS_COMPLIANT_WITH_EXEMPTION; Rtd Current: N/A; Rtd Power: 0.063W; Rtd Voltage: 50V; Status: Released; Texas Part Status: Under Review; Type: Resistor; Vendor: VISHAY; Vendor Part Number: CRCW0402220RJNED; Vendor Part Status: Active; WEIGHT: 0.00065g
R15 = RESISTOR: RESISTOR, THICK FILM, 180, -5%/+5%, 0.063W, 50V, -55DEGC/+155DEGC, 0402, SMD; Additional Datasheet URL: N/A; AutoDoc File: https://notefied-dynamic-precision.com/DB/Apps/Desktop/Item/Object.aspx?id=113318; BU Name: TEXAS INSTRUMENTS NORWAY; Budget Currency: EUR; Budget Price: 0.014; Budgetary Price: 0.014 EUR; Client Status: UNDER_REVIEW; Country of Origin: Missing Info; Datasheet URL: https://www.vishay.com/docs/20035/dcrcwe3.pdf; Datasheet URL 1: http://www.vishay.com/docs/20035/dcrcwe3.pdf; Datasheet URL 2: N/A; Definied Quality: INDUSTRIAL; Esd Level: N/A; Exclusive for Customers: TEXAS INSTRUMENTS NORWAY; Lead Time: 18; LifeCycle Status: ACTIVE; MPN: RESISTOR_0402_180_+/-5%_50V_0.063W_M_+/-200ppm; MPN Status: ACTIVE; MSL: N/A; MTBF: N/A; MTBF Standard: N/A; Manufacturer: MANUFACTURER SELECTION; Mass: 0.00065g; Max Oper Temp: +155DEGC; Max TC: +200PPM/DEGC; Max Tol: +5%; Maximum Operating Temperature: +155DEGC; Maximum Temperature Coefficient: +200PPM/DEGC; Maximum Tolerance: +5%; Min Oper Temp: -55DEGC; Min TC: -200PPM/DEGC; Min Tol: -5%; Minimum Operating Temperature: -55DEGC; Minimum Temperature Coeficient: -200PPM/DEGC; Minimum Tolerance: -5%; Mounting Type: SMD; NOTE Status: PREFERRED; NOTEfied URL: https://notefied-dynamic-precision.com/NOTEfiedWebInterface/part/show?partNumber=01-22345; Notes: Standard item: Duplicate Reason: custom footprint for TEXAS INSTRUMENTS NORWAY.; Old Footprint: RESC1005X40N; PCB Package: 0402; Packing Size: 10000; Packing Type: Tape & Reel; Part Number: 01-22345; Part Type: Resistor|0402|STANDARD; REACH/SVHC Compliance: Compliant; REACH/SVHC Details: SVHC List Version Jun 20, 2016; REACH/SVHC Source: Material Declaration; REACH/SVHC Status: Unaffected; REACH/SVHC_COMPLIANCE: COMPLIANT; REACH/SVHC_DETAILS: SVHC LIST VERSION Jun 20, 2016; REACH/SVHC_SOURCE: MATERIAL DECLARATION; REACH/SVHC_STATUS: UNAFFECTED; ROHS: Exempt; Rated Current: N/A; Rated Power: 0.063W; Rated Voltage: 50V; Resistor Type: THICK FILM; Revision: R021; RoHS Status: ROHS_COMPLIANT_WITH_EXEMPTION; Rtd Current: N/A; Rtd Power: 0.063W; Rtd Voltage: 50V; Status: Released; Texas Part Status: Under Review; Type: Resistor; Vendor: VISHAY; Vendor Part Number: CRCW0402180RJNED; Vendor Part Status: Active; WEIGHT: 0.00065g
R24 = RESISTOR: RESISTOR, THICK FILM, 2.2k, -5%/+5%, 0.063W, 50V, -55DEGC/+155DEGC, 0402, SMD; Additional Datasheet URL: N/A; AutoDoc File: https://notefied-dynamic-precision.com/DB/Apps/Desktop/Item/Object.aspx?id=114560; BU Name: TEXAS INSTRUMENTS NORWAY; Budget Currency: EUR; Budget Price: 0.014; Budgetary Price: 0.014 EUR; Client Status: UNDER_REVIEW; Country of Origin: Israel; Datasheet URL: https://www.vishay.com/docs/20035/dcrcwe3.pdf; Datasheet URL 1: http://www.vishay.com/docs/20035/dcrcwe3.pdf; Datasheet URL 2: N/A; Definied Quality: INDUSTRIAL; Esd Level: N/A; Exclusive for Customers: TEXAS INSTRUMENTS NORWAY; Lead Time: 18; LifeCycle Status: ACTIVE; MPN: RESISTOR_0402_2.2k_+/-5%_50V_0.063W_M_+/-200ppm; MPN Status: ACTIVE; MSL: N/A; MTBF: N/A; MTBF Standard: N/A; Manufacturer: MANUFACTURER SELECTION; Mass: 0.00065g; Max Oper Temp: +155DEGC; Max TC: +200PPM/DEGC; Max Tol: +5%; Maximum Operating Temperature: +155DEGC; Maximum Temperature Coefficient: +200PPM/DEGC; Maximum Tolerance: +5%; Min Oper Temp: -55DEGC; Min TC: -200PPM/DEGC; Min Tol: -5%; Minimum Operating Temperature: -55DEGC; Minimum Temperature Coeficient: -200PPM/DEGC; Minimum Tolerance: -5%; Mounting Type: SMD; NOTE Status: PREFERRED; NOTEfied URL: https://notefied-dynamic-precision.com/NOTEfiedWebInterface/part/show?partNumber=01-22487; Notes: Standard item: Duplicate Reason: custom footprint for TEXAS INSTRUMENTS NORWAY.; Old Footprint: RESC1005X40N; PCB Package: 0402; Packing Size: 10000; Packing Type: Tape & Reel; Part Number: 01-22487; Part Type: Resistor|0402|STANDARD; REACH/SVHC Compliance: Compliant; REACH/SVHC Details: SVHC List Version Jun 20, 2016; REACH/SVHC Source: Material Declaration; REACH/SVHC Status: Unaffected; REACH/SVHC_COMPLIANCE: COMPLIANT; REACH/SVHC_DETAILS: SVHC LIST VERSION Jun 20, 2016; REACH/SVHC_SOURCE: MATERIAL DECLARATION; REACH/SVHC_STATUS: UNAFFECTED; ROHS: Exempt; Rated Current: N/A; Rated Power: 0.063W; Rated Voltage: 50V; Resistor Type: THICK FILM; Revision: R021; RoHS Status: ROHS_COMPLIANT; Rtd Current: N/A; Rtd Power: 0.063W; Rtd Voltage: 50V; Status: Released; Texas Part Status: Under Review; Type: Resistor; Vendor: VISHAY; Vendor Part Number: CRCW04022K20JNED; Vendor Part Status: Active; WEIGHT: 0.00065g
SW1 SW2 = SWITCH_TACT_V2: SWITCH, TACT, 0.05A@12VDC, 0.05A@250VAC, SMD; ALT_SYMBOLS: SW_1188E1K2V_A2L,SW_1188E1K2V_A2M; Additional Datasheet URL: http://www.dip.com.tw/en/en-product-information/en-switch004/item/2445-1188; AutoDoc File: http://notefied-dynamic-precision.com/DB/Apps/Desktop/Item/Object.aspx?id=104642; CLASS: IC; Country of Origin: China,Vietnam; Datasheet URL: http://www.dip.com.tw/en/en-product-information/en-switch004/item/download/2483_bfc264bcfe9982a2b01570916dd931c3; Datasheet URL 1: N/A; Datasheet URL 2: http://www.dip.com.tw/en/en-product-information/en-switch004; FPLIST: SW_1188E1K2V_A2N,SW_1188E1K2V_A2L,SW_1188E1K2V_A2M; MPN: 1188E-1K2-V-TR; MPN Status: ACTIVE; Manufacturer: DIPTRONICS; Mass: N/A; Max Oper Temp: +70DEGC; Maximum Operating Temperature: +70DEGC; Min Oper Temp: -25DEGC; Minimum Operating Temperature: -25DEGC; Mounting Type: SMD; NOTE Status: PREFERRED; NOTEfied URL: https://notefied-dynamic-precision.com/NOTEfiedWebInterface/part/show?partNumber=08-00293; Packing Size: 1500; Packing Type: Tape & Reel; Part Number: 08-00293; Part Type: Switch|TACTILE; REACH/SVHC Compliance: Compliant; REACH/SVHC Details: SVHC List Version Dec 17, 2015; REACH/SVHC Source: REACH Declaration; REACH/SVHC Status: Unaffected; ROHS: Compliant; Rated Current: 0.05A; Rated Voltage: 12VDC; Revision: R021; RoHS Status: ROHS_COMPLIANT; Rtd Current: 0.05A; Rtd Voltage: 12V; Status: Released; Texas Part Status: Under Review; Type: Switch; Vendor: DIPTRONICS; Vendor Part Number: 1188E-1K2-V-TR; Vendor Part Status: Active
U1 = IC_RF_CC2652PSIP_LGA73: IC, CUSTOM, CC2652PSIP, LGA73, SMD; Additional Datasheet URL: N/A; Datasheet URL: N/A; Mass: N/A; Maximum Operating Temperature: N/A; Minimum Operating Temperature: N/A; Mounting Type: SMD; NOTEfied URL: https://notefied-dynamic-precision.com/NOTEfiedWebInterface/part/show?partNumber=18-37194; Notes: Custom preliminary item; PCB Package: LGA73; Packing Size: N/A; Packing Type: Missing Info; Part Number: 18-37194; Part Type: IC|CUSTOM; REACH/SVHC Compliance: Missing Info; REACH/SVHC Details: N/A; REACH/SVHC Source: N/A; REACH/SVHC Status: Missing Info; ROHS: Missing Info; Revision: R002; Status: Released; Texas Part Status: Under Review; Type: IC; Vendor: TEXAS INSTRUMENTS; Vendor Part Number: CC2652PSIP; Vendor Part Status: Active
U3 = IC_FLASH_MX25R8035F_USON8: IC, MEMORY, FLASH, SERIAL, 8Mbit, 1.65V TO 3.6V, USON8, SMD; ALT_SYMBOLS: SON50P300X200X60-9B2L,SON50P300X200X60-9B2M; Additional Datasheet URL: https://www.macronix.com/en-us/products/NOR-Flash/Serial-NOR-Flash/Pages/spec.aspx?p=MX25R8035F&m=Serial%20NOR%20Flash&n=PM2164; AutoDoc File: http://notefied-dynamic-precision.com/DB/Apps/Desktop/Item/Object.aspx?id=104624; Budgetary Price: 0.42218 USD; Country of Origin: Taiwan; Datasheet URL: https://www.macronix.com/Lists/Datasheet/Attachments/7934/MX25R8035F,%20Wide%20Range,%208Mb,%20v1.6.pdf; Datasheet URL 1: N/A; Datasheet URL 2: http://www.macronix.com/Lists/DataSheet/Attachments/2570/MX25R8035F,%20Wide%20Range,%208Mb,%20v0.04.pdf; FPLIST: SON50P300X200X60-9B2N,SON50P300X200X60-9B2L,SON50P300X200X60-9B2M; Lead Time: 10; MPN Status: ACTIVE; Manufacturer: MACRONIX; Mass: N/A; Max Oper Temp: +85DEGC; Maximum Operating Temperature: +85DEGC; Min Oper Temp: -40DEGC; Minimum Operating Temperature: -40DEGC; Mounting Type: SMD; NOTE Status: PREFERRED; NOTEfied URL: https://notefied-dynamic-precision.com/NOTEfiedWebInterface/part/show?partNumber=18-31726; PCB Package: uSON8; Packing Size: 100; Packing Type: Tube; Part Number: 18-31726; Part Type: IC|MEMORY|FLASH|OTHER; REACH/SVHC Compliance: Compliant; REACH/SVHC Details: N/A; REACH/SVHC Source: REACH Declaration & Material Declaration; REACH/SVHC Status: Unaffected; ROHS: Compliant; Rated Voltage: 1.65V TO 3.6V; Revision: R022; RoHS Status: ROHS_COMPLIANT; Rtd Voltage: 1.65V TO 3.6V; Status: Released; Texas Part Status: Under Review; Type: IC; Vendor: MACRONIX; Vendor Part Status: Active
U4 = IC_EEPROM_CAT24C08_TSOT23-5: IC, MEMORY, EEPROM, SERIAL, I2C, CMOS, 8kbit, 1.7V TO 5.5V, TSOT23-5, SMD; ALT_SYMBOLS: SOT95P280X100-5A2L,SOT95P280X100-5A2M; Additional Datasheet URL: https://www.onsemi.com/pub/Collateral/419AE.PDF; Budgetary Price: 0.1867 USD; Datasheet URL: https://www.onsemi.com/pub/Collateral/CAT24C01-D.PDF; Mass: 0.01268g; Maximum Operating Temperature: +85DEGC; Minimum Operating Temperature: -40DEGC; Mounting Type: SMD; NOTEfied URL: https://notefied-dynamic-precision.com/NOTEfiedWebInterface/part/show?partNumber=18-36044; PCB Package: TSOT23-5; Packing Size: 3000; Packing Type: Tape & Reel; Part Number: 18-36044; Part Type: IC|MEMORY|ROM|EEPROM|SERIAL|I2C; REACH/SVHC Compliance: Compliant; REACH/SVHC Details: SVHC List Version Jan 16, 2020; REACH/SVHC Source: REACH Declaration; REACH/SVHC Status: Unaffected; ROHS: Compliant; Rated Voltage: 1.7V TO 5.5V; Revision: R004; Status: Released; Texas Part Status: Under Review; Type: IC; Vendor: ON SEMICONDUCTOR; Vendor Part Number: CAT24C08TDI-GT3; Vendor Part Status: Active
Z9 = CAPACITOR: CAPACITOR, CERAMIC C0G/NP0, 5.6pF, 50V, -0.1pF/+0.1pF, -55DEGC/+125DEGC, 0201, SMD; ALT_SYMBOLS: CAPC0603X35B2L,CAPC0603X35B2M; Additional Datasheet URL: https://search.murata.co.jp/Ceramy/image/img/A01X/G101/ENG/GRM0335C1H5R6BA01-01A.pdf; Budgetary Price: 0.00272 USD; Country of Origin: Missing Info; Datasheet URL: https://www.murata.com/-/media/webrenewal/support/library/catalog/products/capacitor/mlcc/c02e.ashx?la=en-gb; Dielectric Type: C0G/NP0; Lead Time: 11; Mass: 0.00033g; Maximum Operating Temperature: +125DEGC; Maximum Tolerance: +0.1pF; Minimum Operating Temperature: -55DEGC; Minimum Tolerance: -0.1pF; Mounting Type: SMD; NOTEfied URL: https://notefied-dynamic-precision.com/NOTEfiedWebInterface/part/show?partNumber=02-06170; PCB Package: 0201; Packing Size: 50000; Packing Type: Tape & Reel; Part Number: 02-06170; Part Type: Capacitor|CERAMIC|0201|STANDARD; REACH/SVHC Compliance: Compliant; REACH/SVHC Details: SVHC List Version Jul 7, 2017; REACH/SVHC Source: REACH Declaration; REACH/SVHC Status: Unaffected; ROHS: Compliant; Rated Voltage: 50V; Revision: R025; Status: Released; Texas Part Status: Under Review; Type: Capacitor; Vendor: MURATA; Vendor Part Number: GRM0335C1H5R6BA01J; Vendor Part Status: Active
Z10 = INDUCTOR: INDUCTOR, RF, CHIP, NON-MAGNETIC CORE, 8.2nH, -5%/+5%, 0.25A, -55DEGC/+125DEGC, 0201, SMD; ALT_SYMBOLS: INDC0603X33A2L,INDC0603X33A2M; Additional Datasheet URL: https://search.murata.co.jp/Ceramy/image/img/P02/JELF243C-0015.pdf; Country of Origin: Japan; Datasheet URL: http://www.murata.com/en-eu/api/pdfdownloadapi?cate=cgInductors&partno=LQP03TN8N2J02%23; Frequency: 3600MHz; Mass: 0.0002g; Maximum Operating Temperature: +125DEGC; Maximum Tolerance: +5%; Minimum Operating Temperature: -55DEGC; Minimum Tolerance: -5%; Mounting Type: SMD; NOTEfied URL: https://notefied-dynamic-precision.com/NOTEfiedWebInterface/part/show?partNumber=03-08085; PCB Package: 0201; Packing Size: 15000; Packing Type: Tape & Reel; Part Number: 03-08085; Part Type: Inductor|RF|CHIP|0201; REACH/SVHC Compliance: Compliant; REACH/SVHC Details: SVHC List Version Jul 16, 2019; REACH/SVHC Source: REACH Declaration; REACH/SVHC Status: Unaffected; ROHS: Compliant; Rated Current: 0.25A; Resistance: 0.7; Revision: R016; Status: Released; Texas Part Status: Under Review; Type: Inductor; Vendor: MURATA; Vendor Part Number: LQP03TN8N2J02D; Vendor Part Status: Active
Z11 = CAPACITOR: CAPACITOR, CERAMIC C0G/NP0, 1.8pF, 50V, -0.1pF/+0.1pF, -55DEGC/+125DEGC, 0201, SMD; ALT_SYMBOLS: CAPC0603X35B2L,CAPC0603X35B2M; Additional Datasheet URL: https://search.murata.co.jp/Ceramy/image/img/A01X/G101/ENG/GRM0335C1H1R8BA01-01A.pdf; Budgetary Price: 0.01 EUR; Country of Origin: China,Japan,Philippines; Datasheet URL: http://www.murata.com/en-eu/api/pdfdownloadapi?cate=luCeramicCapacitorsSMD&partno=GRM0335C1H1R8BA01%23; Dielectric Type: C0G/NP0; Lead Time: 24; Mass: 0.00033g; Maximum Operating Temperature: +125DEGC; Maximum Tolerance: +0.1pF; Minimum Operating Temperature: -55DEGC; Minimum Tolerance: -0.1pF; Mounting Type: SMD; NOTEfied URL: https://notefied-dynamic-precision.com/NOTEfiedWebInterface/part/show?partNumber=02-06132; PCB Package: 0201; Packing Size: 50000; Packing Type: Tape & Reel; Part Number: 02-06132; Part Type: Capacitor|CERAMIC|0201|STANDARD; REACH/SVHC Compliance: Compliant; REACH/SVHC Details: SVHC List Version Jul 7, 2017; REACH/SVHC Source: REACH Declaration; REACH/SVHC Status: Unaffected; ROHS: Compliant; Rated Voltage: 50V; Revision: R033; Status: Released; Texas Part Status: Under Review; Type: Capacitor; Vendor: MURATA; Vendor Part Number: GRM0335C1H1R8BA01J; Vendor Part Status: Active

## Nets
5V0_BP: J1.2 J4.18 P2.1 U4.4(VCC)
GND: C1.2 C55.2 CR2.4(GND) CR4.1(C) CR5.1(C) J1.4 J2.2 J4.1 J4.7 J4.13 J4.19 J4.20 J5.2 J5.3 J5.4 J5.5 P2.2 P2.3 P3.2 P3.3 P6.3 P6.5 P6.9 SW1.1 SW1.2 SW1.3 SW2.1 SW2.2 SW2.4 U1.5(GND) U1.9(GND) U1.10(GND) U1.11(GND) U1.12(GND) U1.13(GND) U1.16(GND) U1.17(GND) U1.19(GND) U1.49(GND) U1.50(GND) U1.51(GND) U1.52(GND) U1.53(GND) U1.54(GND) U1.55(GND) U1.56(GND) U1.57(GND) U1.58(GND) U1.59(GND) U1.60(GND) U1.61(GND) U1.62(GND) U1.63(GND) U1.64(GND) U1.65(GND) U1.66(GND) U1.67(GND) U1.68(GND) U1.69(GND) U1.70(GND) U1.71(GND) U1.72(GND) U1.73(GND) U3.4(GND) U3.9(EGP) U4.2(VSS) U4.5(WP) Z9.1 Z11.2 ; also on sheet 2
VDDS: FL2.1 U1.46(VDDS) U1.47(VDDS_PU)
BP_RESET: J2.11 R9.2
DIO1: J1.18 U1.21(DIO1)
DIO2: J1.20 U1.20(DIO2)
DIO4: J2.7 U1.22(DIO4)
DIO5_SDA: J1.19 R2.1 U1.23(DIO5)
DIO6_RLED: J2.3 P1.2 U1.24(DIO6)
DIO7_GLED: J2.1 P1.4 U1.25(DIO7)
DIO8_MISO: J2.14 U1.26(DIO8) U3.2(SO/SIO1)
DIO9_MOSI: J2.12 U1.27(DIO9) U3.5(SI/SIO0)
DIO10_SCLK: J1.13 U1.28(DIO10) U3.6(SCLK)
DIO11_CS: J2.6 U1.29(DIO11)
DIO14_BTN2: J2.18 R13.2 U1.32(DIO14)
DIO15_BTN1: J2.16 R12.2 U1.33(DIO15)
DIO19_CTS: J2.4 U1.40(DIO19)
DIO20_Flash_CS: J2.5 R24.1 U1.41(DIO20) U3.1(nCS)
DIO21_SCL: J1.17 R3.1 U1.42(DIO21)
DIO22: J1.9 U1.43(DIO22)
DIO23_Analog: J1.3 U1.44(DIO23)
DIO24_Analog: J1.11 U1.45(DIO24)
DIO25_Analog: J1.6 U1.48(DIO25)
DIO26_Analog: J1.8 U1.1(DIO26)
DIO27_Analog: J1.10 U1.2(DIO27)
DIO28: J1.12 U1.3(DIO28)
DIO29: J1.14 U1.7(DIO29)
DIO30: J1.16 U1.8(DIO30)
DIO31: J1.15 U1.38(DIO31)
LP_RESET: J2.10 R11.2
RESET: CR2.2(IO2) J4.10 P6.10 R9.1 R11.1 U1.4(nRESET)
RXD: J1.5 J4.14 U1.30(DIO12)
SWO: CR2.1(IO1) J2.9 J4.11 U1.39(DIO18)
TCK: CR2.6(IO5) J4.6 P6.4 R5.2 U1.35(TCK)
TDI: CR2.3(IO3) J4.2 P6.8 R7.2 U1.37(DIO17)
TDO: CR2.5(IO4) J4.4 P6.6 R6.2 U1.36(DIO16)
TMS: CR2.7(IO6) J4.8 P6.2 R4.2 U1.34(TMS)
TXD: J1.7 J4.12 U1.31(DIO13)
WMCU_VDD: CR2.8(VCC) FL2.2 J1.1 J4.16 P3.1 P6.1 R2.2 R3.2 R22.2 R23.2 R24.2 R25.1
XDS_BoardID_SCL: J4.15 U4.1(SCL)
XDS_BoardID_SDA: J4.17 U4.3(SDA)
N3109894: J2.13 R4.1
N3109960: J2.15 R5.1
N3110034: J2.17 R6.1
N3110086: J2.19 R7.1
N3110356: P1.1 R15.2
N3110380: P1.3 R14.2
N3110768: R12.1 SW1.4
N3110772: R13.1 SW2.3
N3110876: CR4.2(A) R14.1
N3110880: CR5.2(A) R15.1
N3111246: C55.1 R25.2 U3.8(VCC)
N3111262: R22.1 U3.7(nRST/SIO3)
N3111266: R23.1 U3.3(nWP/SIO2)
N3450237: C56.1 J5.1
N3450301: C1.1 C56.2 C57.1 L1.2
N3495961: C57.2 Z9.2 Z10.1
N3495979: A2.1 Z10.2 Z11.1
N3510597: L1.1 U1.18(RF)

Not connected (* = marked no-connect by the designer): J2 8* 20*; J4 3 5 9; P6 7*; U1 6(TP_VDDR) 14(DIO0) 15(DIO3)

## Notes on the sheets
sheet 1
- Booster Pack Headers
- Power Headers
- XDS110 Header
- 1
- 2
- 21
- 40
- 20
- 3
- 22
- 23
- 38
- 39
- 18
- 19
- 4
- 24
- 37
- 17
- 5
- 25
- 36
- 16
- 6
- 26
- 35
- 15
- 7
- 27
- 34
- 14
- 8
- 9
- 28
- 29
- 32
- 33
- 12
- 13
- 10
- 30
- 31
- 11
- DEBUG
- Wireless MCU
- Only for 20 dBm 868 MHz
  Optional filtering 915 MHz
- Switch between
  SMA or Antenna
- Antenna Match
- Buttons / LEDs
- External flash
- Board ID
